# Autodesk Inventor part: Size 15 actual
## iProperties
Created: 2006-11
Part Number: Size 15 actual
Document SubType Name: Modeling
Designer: Andrew DuBuc
Density: 1 g/cm^3
Author: Andrew DuBuc
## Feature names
1. Revolution1
